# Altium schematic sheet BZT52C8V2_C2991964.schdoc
size 127 x 101 mm
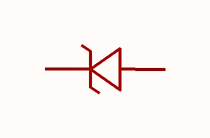
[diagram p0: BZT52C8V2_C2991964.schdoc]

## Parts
U?  bzt52c8v2_c2991964  [SOD-123_L2.7-W1.6-LS3.7-RD-1]  (value not drawn)

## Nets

Not connected (* = marked no-connect by the designer): U? 1(K) 2(A)

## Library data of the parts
U? = bzt52c8v2_c2991964: 二极管配置:1个独立式;稳压值(标称值):8.2V;稳压值(范围):7.7V~8.7V;耗散功率(Pd):500mW;; Manufacturer: CJ(江苏长电/长晶); AddInBom: yes; ModelId: 528459655f7d4601a76356f3191c812b; ModelTransform: 151.575,66.929,0,0,0,0,0,0,0; Diode Configuration: 1个独立式; Zener Voltage(Nom): 8.2V; Reverse Leakage Current (Ir): 700nA; Pd - Power Dissipation: 500mW; Impedance(Zzt): 15Ω; Impedance(Zzk): 80Ω; Operating Junction Temperature Range: -55℃~+150℃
